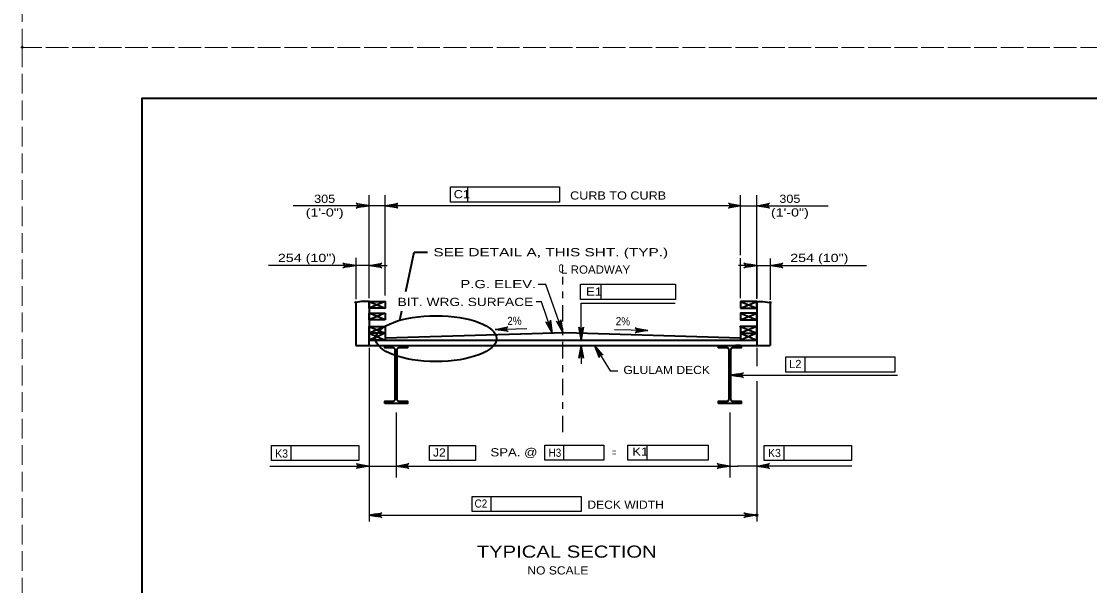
# Model space of a CAD drawing. Extents: x -11 to 79, y -154 to 0.
# Drawn here: x -0.01 to 15.61, y -73.87 to -65.62 of the extents above; entities that cross this region are included whole.
import ezdxf
from ezdxf.enums import TextEntityAlignment as Align

# ---------------------------------------------------------------- set-up
doc = ezdxf.new("R2010")
doc.units = 0
doc.header["$LTSCALE"] = 0.048
doc.header["$PDMODE"] = 32
doc.header["$PDSIZE"] = 0.024
doc.linetypes.add('DOT_DASHED', pattern=[7.7, 5, -1.2, 0.3, -1.2])
doc.linetypes.add('LONG_DASHED', pattern=[7.5, 6, -1.5])
for name, color, linetype, lineweight in [('1', 7, 'Continuous', 25), ('2', 7, 'Continuous', 35), ('3', 7, 'Continuous', 25), ('4', 7, 'Continuous', 25), ('6', 7, 'Continuous', 25), ('63', 7, 'LONG_DASHED', 13)]:
    doc.layers.add(name, color=color, linetype=linetype, lineweight=lineweight)
doc.layers.add('62', color=7, linetype='Continuous')

msp = doc.modelspace()

# ---------------------------------------------------------------- hatches: boundary and pattern name
at = {"layer": '2'}
for points in [[(4.96025, -68.29692), (4.96025, -68.33475), (5.07358, -68.31583)], [(10.39333, -68.29692), (10.39333, -68.33475), (10.50675, -68.31583)], [(10.85633, -68.29692), (10.85633, -68.33475), (10.74292, -68.31583)], [(4.76433, -69.173), (4.76433, -69.21083), (4.87767, -69.19192)], [(5.187, -69.173), (5.187, -69.21083), (5.07358, -69.19192)], [(10.62958, -69.173), (10.62958, -69.21083), (10.74292, -69.19192)], [(11.05225, -69.173), (11.05225, -69.21083), (10.93883, -69.19192)], [(7.05317, -70.14167), (7.05217, -70.10383), (6.93925, -70.12575)], [(8.98917, -70.12025), (8.98817, -70.158), (9.102, -70.14208)], [(8.19275, -70.16133), (8.155, -70.16133), (8.17392, -70.27475)], [(8.15583, -70.477), (8.19367, -70.477), (8.17475, -70.36358)], [(5.58075, -72.10567), (5.58075, -72.1435), (5.46733, -72.12458)], [(10.23583, -72.10567), (10.23583, -72.1435), (10.34925, -72.12458)], [(5.17875, -72.86108), (5.17875, -72.82608), (5.07358, -72.84358)], [(10.63775, -72.86108), (10.63775, -72.82608), (10.74292, -72.84358)]]:
    msp.add_hatch(color=256, dxfattribs=at).paths.add_polyline_path(points)
at = {"layer": '4'}
for points in [[(7.73375, -70.06542), (7.69808, -70.07792), (7.7535, -70.17867)], [(7.8885, -70.061), (7.85283, -70.0735), (7.90825, -70.17425)], [(8.41383, -70.46658), (8.44608, -70.44683), (8.37075, -70.36)], [(10.474, -70.81392), (10.474, -70.77617), (10.36067, -70.79508)]]:
    msp.add_hatch(color=256, dxfattribs=at).paths.add_polyline_path(points)
at = {"layer": '6'}
msp.add_hatch(color=256, dxfattribs=at).paths.add_polyline_path([(5.42325, -68.33475), (5.42325, -68.29692), (5.30983, -68.31583)])

# ---------------------------------------------------------------- linework, layer by layer
at = {"layer": '1', "lineweight": 35}
msp.add_lwpolyline([(1.75, -87.25), (33.25, -87.25), (33.25, -66.75), (1.75, -66.75)], close=True, dxfattribs=at)
at = {"layer": '2', "lineweight": 25}
for p, q in [((5.07358, -69.077), (5.07358, -68.16183)), ((5.30983, -69.62908), (5.30983, -68.16183)), ((10.50675, -69.038), (10.50675, -68.16183)), ((10.74292, -69.077), (10.74292, -68.16183)), ((5.30983, -68.31583), (3.96233, -68.31583)), ((10.39333, -68.31583), (5.30983, -68.31583)), ((10.50675, -68.31583), (11.78625, -68.31583)), ((5.07358, -69.19192), (3.60142, -69.19192)), ((4.87767, -69.07975), (4.87767, -69.68458)), ((5.07358, -69.67008), (5.07358, -69.08308)), ((5.187, -69.19192), (5.33975, -69.19192)), ((10.62958, -69.19192), (10.47683, -69.19192)), ((10.50675, -69.66767), (10.50675, -69.08308)), ((10.74292, -69.67675), (10.74292, -69.08308)), ((10.74292, -69.19192), (12.34925, -69.19192)), ((10.74292, -69.19508), (10.74292, -69.66633)), ((10.93883, -69.0905), (10.93883, -69.69183)), ((8.17392, -69.74075), (9.55233, -69.74075)), ((8.17392, -70.28133), (8.17392, -69.74075)), ((6.91817, -70.12625), (7.37992, -70.11425)), ((9.15258, -70.14375), (8.66308, -70.13008)), ((5.07358, -70.39292), (5.07358, -72.93825)), ((8.17475, -70.36), (8.17475, -70.62758)), ((10.74292, -70.39367), (10.74292, -70.66308)), ((10.74292, -70.88375), (10.74292, -72.93825)), ((5.46733, -71.33975), (5.46733, -72.23875)), ((10.34925, -71.33975), (10.34925, -72.23875)), ((5.46733, -71.88817), (5.46733, -72.29467)), ((10.34925, -71.88817), (10.34925, -72.29467)), ((3.62392, -72.12458), (5.07358, -72.12458)), ((5.07358, -72.12458), (10.472, -72.12458)), ((12.13342, -72.12458), (10.46258, -72.12458)), ((5.07358, -72.84358), (10.74292, -72.84358))]:
    msp.add_line(p, q, dxfattribs=at)
at = {"layer": '2', "linetype": 'DOT_DASHED', "lineweight": 25}
msp.add_line((7.90825, -71.62917), (7.90825, -69.35858), dxfattribs=at)
at = {"layer": '2', "lineweight": 25}
for points in [[(5.07008, -68.31525), (4.88367, -68.35017), (4.898, -68.34025), (4.90542, -68.32775), (4.90758, -68.31525), (4.90542, -68.30275), (4.898, -68.29025), (4.88367, -68.28033), (5.07008, -68.31525), (4.898, -68.29025), (4.90542, -68.30275), (5.07008, -68.31525), (4.90758, -68.31525), (4.90542, -68.32775), (5.07008, -68.31525), (4.898, -68.34025)], [(5.30983, -68.31583), (5.49625, -68.28092), (5.48192, -68.29083), (5.4745, -68.30333), (5.47233, -68.31583), (5.4745, -68.32833), (5.48192, -68.34083), (5.49625, -68.35075), (5.30983, -68.31583), (5.48192, -68.34083), (5.4745, -68.32833), (5.30983, -68.31583), (5.47233, -68.31583), (5.4745, -68.30333), (5.30983, -68.31583), (5.48192, -68.29083)], [(10.51717, -68.31583), (10.33075, -68.35075), (10.34508, -68.34083), (10.3525, -68.32833), (10.35467, -68.31583), (10.3525, -68.30333), (10.34508, -68.29083), (10.33075, -68.28092), (10.51717, -68.31583), (10.34508, -68.29083), (10.3525, -68.30333), (10.51717, -68.31583), (10.35467, -68.31583), (10.3525, -68.32833), (10.51717, -68.31583), (10.34508, -68.34083)], [(10.74292, -68.31583), (10.92933, -68.28092), (10.915, -68.29083), (10.90758, -68.30333), (10.90542, -68.31583), (10.90758, -68.32833), (10.915, -68.34083), (10.92933, -68.35075), (10.74292, -68.31583), (10.915, -68.34083), (10.90758, -68.32833), (10.74292, -68.31583), (10.90542, -68.31583), (10.90758, -68.30333), (10.74292, -68.31583), (10.915, -68.29083)], [(4.87767, -69.19192), (4.69125, -69.22683), (4.70558, -69.21692), (4.713, -69.20442), (4.71517, -69.19192), (4.713, -69.17942), (4.70558, -69.16692), (4.69125, -69.157), (4.87767, -69.19192), (4.70558, -69.16692), (4.713, -69.17942), (4.87767, -69.19192), (4.71517, -69.19192), (4.713, -69.20442), (4.87767, -69.19192), (4.70558, -69.21692)], [(5.07358, -69.19192), (5.26, -69.157), (5.24567, -69.16692), (5.23825, -69.17942), (5.23608, -69.19192), (5.23825, -69.20442), (5.24567, -69.21692), (5.26, -69.22683), (5.07358, -69.19192), (5.24567, -69.21692), (5.23825, -69.20442), (5.07358, -69.19192), (5.23608, -69.19192), (5.23825, -69.17942), (5.07358, -69.19192), (5.24567, -69.16692)], [(10.74292, -69.19192), (10.5565, -69.22683), (10.57083, -69.21692), (10.57825, -69.20442), (10.58042, -69.19192), (10.57825, -69.17942), (10.57083, -69.16692), (10.5565, -69.157), (10.74292, -69.19192), (10.57083, -69.16692), (10.57825, -69.17942), (10.74292, -69.19192), (10.58042, -69.19192), (10.57825, -69.20442), (10.74292, -69.19192), (10.57083, -69.21692)], [(10.93883, -69.19192), (11.12525, -69.157), (11.11092, -69.16692), (11.1035, -69.17942), (11.10133, -69.19192), (11.1035, -69.20442), (11.11092, -69.21692), (11.12525, -69.22683), (10.93883, -69.19192), (11.11092, -69.21692), (11.1035, -69.20442), (10.93883, -69.19192), (11.10133, -69.19192), (11.1035, -69.17942), (10.93883, -69.19192), (11.11092, -69.16692)], [(7.7535, -70.17867), (7.65875, -70.01433), (7.67292, -70.02458), (7.68717, -70.0275), (7.69967, -70.02533), (7.71075, -70.01917), (7.72008, -70.00808), (7.72475, -69.99117), (7.7535, -70.17867), (7.72008, -70.00808), (7.71075, -70.01917), (7.7535, -70.17867), (7.69967, -70.02533), (7.68717, -70.0275), (7.7535, -70.17867), (7.67292, -70.02458)], [(7.90742, -70.17192), (7.81267, -70.00758), (7.82683, -70.01783), (7.84108, -70.02075), (7.85358, -70.01858), (7.86467, -70.01242), (7.874, -70.00133), (7.87867, -69.98442), (7.90742, -70.17192), (7.874, -70.00133), (7.86467, -70.01242), (7.90742, -70.17192), (7.85358, -70.01858), (7.84108, -70.02075), (7.90742, -70.17192), (7.82683, -70.01783)], [(6.91817, -70.12625), (7.10358, -70.0865), (7.0895, -70.09675), (7.08242, -70.1095), (7.08058, -70.122), (7.08308, -70.1345), (7.09083, -70.14675), (7.10542, -70.15633), (6.91817, -70.12625), (7.09083, -70.14675), (7.08308, -70.1345), (6.91817, -70.12625), (7.08058, -70.122), (7.08242, -70.1095), (6.91817, -70.12625), (7.0895, -70.09675)], [(8.17392, -70.28133), (8.139, -70.09492), (8.14892, -70.10925), (8.16142, -70.11667), (8.17392, -70.11883), (8.18642, -70.11667), (8.19892, -70.10925), (8.20883, -70.09492), (8.17392, -70.28133), (8.19892, -70.10925), (8.18642, -70.11667), (8.17392, -70.28133), (8.17392, -70.11883), (8.16142, -70.11667), (8.17392, -70.28133), (8.14892, -70.10925)], [(9.15258, -70.14375), (8.96525, -70.1735), (8.97992, -70.16392), (8.98767, -70.15167), (8.99017, -70.13925), (8.98833, -70.12667), (8.98133, -70.11392), (8.96725, -70.10358), (9.15258, -70.14375), (8.98133, -70.11392), (8.98833, -70.12667), (9.15258, -70.14375), (8.99017, -70.13925), (8.98767, -70.15167), (9.15258, -70.14375), (8.97992, -70.16392)], [(8.17475, -70.36), (8.20967, -70.54642), (8.19975, -70.53208), (8.18725, -70.52467), (8.17475, -70.5225), (8.16225, -70.52467), (8.14975, -70.53208), (8.13983, -70.54642), (8.17475, -70.36), (8.14975, -70.53208), (8.16225, -70.52467), (8.17475, -70.36), (8.17475, -70.5225), (8.18725, -70.52467), (8.17475, -70.36), (8.19975, -70.53208)], [(8.37067, -70.36), (8.49783, -70.50075), (8.48183, -70.49367), (8.46733, -70.49392), (8.4555, -70.49858), (8.446, -70.50692), (8.43917, -70.51975), (8.43817, -70.53725), (8.37067, -70.36), (8.43917, -70.51975), (8.446, -70.50692), (8.37067, -70.36), (8.4555, -70.49858), (8.46733, -70.49392), (8.37067, -70.36), (8.48183, -70.49367)], [(10.36067, -70.79508), (10.54708, -70.76017), (10.53275, -70.77008), (10.52533, -70.78258), (10.52317, -70.79508), (10.52533, -70.80758), (10.53275, -70.82008), (10.54708, -70.83), (10.36067, -70.79508), (10.53275, -70.82008), (10.52533, -70.80758), (10.36067, -70.79508), (10.52317, -70.79508), (10.52533, -70.78258), (10.36067, -70.79508), (10.53275, -70.77008)], [(5.07358, -72.12458), (4.88717, -72.1595), (4.9015, -72.14958), (4.90892, -72.13708), (4.91108, -72.12458), (4.90892, -72.11208), (4.9015, -72.09958), (4.88717, -72.08967), (5.07358, -72.12458), (4.9015, -72.09958), (4.90892, -72.11208), (5.07358, -72.12458), (4.91108, -72.12458), (4.90892, -72.13708), (5.07358, -72.12458), (4.9015, -72.14958)], [(5.46733, -72.12458), (5.65375, -72.08967), (5.63942, -72.09958), (5.632, -72.11208), (5.62983, -72.12458), (5.632, -72.13708), (5.63942, -72.14958), (5.65375, -72.1595), (5.46733, -72.12458), (5.63942, -72.14958), (5.632, -72.13708), (5.46733, -72.12458), (5.62983, -72.12458), (5.632, -72.11208), (5.46733, -72.12458), (5.63942, -72.09958)], [(10.34925, -72.12458), (10.16283, -72.1595), (10.17717, -72.14958), (10.18458, -72.13708), (10.18675, -72.12458), (10.18458, -72.11208), (10.17717, -72.09958), (10.16283, -72.08967), (10.34925, -72.12458), (10.17717, -72.09958), (10.18458, -72.11208), (10.34925, -72.12458), (10.18675, -72.12458), (10.18458, -72.13708), (10.34925, -72.12458), (10.17717, -72.14958)], [(10.74292, -72.12458), (10.92933, -72.08967), (10.915, -72.09958), (10.90758, -72.11208), (10.90542, -72.12458), (10.90758, -72.13708), (10.915, -72.14958), (10.92933, -72.1595), (10.74292, -72.12458), (10.915, -72.14958), (10.90758, -72.13708), (10.74292, -72.12458), (10.90542, -72.12458), (10.90758, -72.11208), (10.74292, -72.12458), (10.915, -72.09958)], [(5.07358, -72.84358), (5.26, -72.80867), (5.24567, -72.81858), (5.23825, -72.83108), (5.23608, -72.84358), (5.23825, -72.85608), (5.24567, -72.86858), (5.26, -72.8785), (5.07358, -72.84358), (5.24567, -72.86858), (5.23825, -72.85608), (5.07358, -72.84358), (5.23608, -72.84358), (5.23825, -72.83108), (5.07358, -72.84358), (5.24567, -72.81858)], [(10.74292, -72.84358), (10.5565, -72.8785), (10.57083, -72.86858), (10.57825, -72.85608), (10.58042, -72.84358), (10.57825, -72.83108), (10.57083, -72.81858), (10.5565, -72.80867), (10.74292, -72.84358), (10.57083, -72.81858), (10.57825, -72.83108), (10.74292, -72.84358), (10.58042, -72.84358), (10.57825, -72.85608), (10.74292, -72.84358), (10.57083, -72.86858)]]:
    msp.add_lwpolyline(points, dxfattribs=at)
for points in [[(4.96025, -68.29692), (4.96025, -68.33475), (5.07358, -68.31583)], [(10.39333, -68.29692), (10.39333, -68.33475), (10.50675, -68.31583)], [(10.85633, -68.29692), (10.85633, -68.33475), (10.74292, -68.31583)], [(4.76433, -69.173), (4.76433, -69.21083), (4.87767, -69.19192)], [(5.187, -69.173), (5.187, -69.21083), (5.07358, -69.19192)], [(10.62958, -69.173), (10.62958, -69.21083), (10.74292, -69.19192)], [(11.05225, -69.173), (11.05225, -69.21083), (10.93883, -69.19192)], [(7.05317, -70.14167), (7.05217, -70.10383), (6.93925, -70.12575)], [(8.98917, -70.12025), (8.98817, -70.158), (9.102, -70.14208)], [(8.19275, -70.16133), (8.155, -70.16133), (8.17392, -70.27475)], [(8.15583, -70.477), (8.19367, -70.477), (8.17475, -70.36358)], [(5.58075, -72.10567), (5.58075, -72.1435), (5.46733, -72.12458)], [(10.23583, -72.10567), (10.23583, -72.1435), (10.34925, -72.12458)], [(5.17875, -72.86108), (5.17875, -72.82608), (5.07358, -72.84358)], [(10.63775, -72.86108), (10.63775, -72.82608), (10.74292, -72.84358)]]:
    msp.add_lwpolyline(points, close=True, dxfattribs=at)
at = {"layer": '2'}
msp.add_point((10.74292, -72.84358), dxfattribs=at)
at = {"layer": '3', "lineweight": 35}
for p, q in [((4.87767, -69.73183), (4.87767, -70.36)), ((5.07358, -69.71542), (5.07358, -70.28133)), ((5.30983, -69.71542), (5.07358, -69.81383)), ((5.07358, -69.71542), (5.30983, -69.81383)), ((10.50675, -69.71542), (10.50675, -69.81383)), ((10.74292, -69.71542), (10.50675, -69.71542)), ((10.50675, -69.81383), (10.74292, -69.71542)), ((10.50675, -69.71542), (10.74292, -69.81383)), ((10.50675, -69.81383), (10.74292, -69.81383)), ((10.74292, -69.71542), (10.74292, -70.36)), ((10.74292, -69.71542), (10.82492, -69.71542)), ((10.74292, -69.81383), (10.74292, -69.71542)), ((10.82492, -69.71542), (10.93883, -69.73183)), ((10.93883, -69.73183), (10.93883, -70.36)), ((5.07358, -69.98608), (5.07358, -69.88767)), ((5.07358, -69.88767), (5.30983, -69.88767)), ((5.30983, -69.88767), (5.07358, -69.98608)), ((5.30983, -69.98608), (5.07358, -69.88767)), ((5.30983, -69.98608), (5.07358, -69.98608)), ((5.30983, -69.88767), (5.30983, -69.98608)), ((10.50675, -69.88767), (10.74292, -69.98608)), ((10.50675, -69.98608), (10.74292, -69.88767)), ((5.07358, -70.18292), (5.07358, -70.0845)), ((5.07358, -70.0845), (5.30983, -70.0845)), ((5.30983, -70.0845), (5.07358, -70.18292)), ((5.30983, -70.0845), (5.30983, -70.18292)), ((10.50675, -70.0845), (10.50675, -70.18292)), ((10.74292, -70.0845), (10.50675, -70.0845)), ((10.50675, -70.0845), (10.74292, -70.18292)), ((10.74292, -70.18292), (10.74292, -70.0845)), ((5.07358, -70.36), (5.07358, -70.18292)), ((5.30983, -70.18292), (5.07358, -70.18292)), ((5.07358, -70.18292), (5.30983, -70.28133)), ((5.07358, -70.28133), (10.50675, -70.28133)), ((5.30983, -70.28133), (5.08892, -70.28133)), ((5.30983, -70.24858), (7.94767, -70.17308)), ((5.30983, -70.18292), (5.30983, -70.28133)), ((7.94767, -70.17308), (10.50675, -70.24858)), ((10.50675, -70.18292), (10.50675, -70.28133)), ((10.50675, -70.18292), (10.74292, -70.18292)), ((10.74292, -70.18292), (10.50675, -70.28133)), ((4.87767, -70.36), (10.93883, -70.36)), ((5.38533, -70.36), (5.54933, -70.36)), ((5.45592, -71.14508), (5.45592, -70.42617)), ((5.47875, -70.42617), (5.47875, -71.14508)), ((10.26725, -70.36), (10.43125, -70.36)), ((10.33783, -71.14508), (10.33783, -70.42617)), ((10.36067, -70.42617), (10.36067, -71.14508)), ((10.50342, -70.36), (10.43125, -70.36))]:
    msp.add_line(p, q, dxfattribs=at)
for points in [[(5.07358, -69.71542), (4.95975, -69.71542), (4.87767, -69.73183)], [(5.07358, -70.0845), (5.30983, -70.18292), (5.07358, -70.28133)], [(10.74292, -70.0845), (10.50675, -70.18292), (10.74292, -70.28133)], [(10.50675, -70.28133), (10.74292, -70.28133), (10.74292, -70.18292)], [(5.42642, -70.39667), (5.30158, -70.39667), (5.30158, -70.36), (5.63308, -70.36), (5.63308, -70.39667), (5.50825, -70.39667)], [(10.30825, -70.39667), (10.1835, -70.39667), (10.1835, -70.36), (10.515, -70.36), (10.515, -70.39667), (10.39017, -70.39667)], [(5.30158, -71.21125), (5.30158, -71.17458), (5.42642, -71.17458)], [(5.50825, -71.17458), (5.63308, -71.17458), (5.63308, -71.21125), (5.30158, -71.21125)], [(10.1835, -71.21125), (10.1835, -71.17458), (10.30825, -71.17458)], [(10.39017, -71.17458), (10.515, -71.17458), (10.515, -71.21125), (10.1835, -71.21125)]]:
    msp.add_lwpolyline(points, dxfattribs=at)
for points in [[(5.07358, -69.71542), (5.30983, -69.71542), (5.30983, -69.81383), (5.07358, -69.81383)], [(10.74292, -69.88767), (10.50675, -69.88767), (10.50675, -69.98608), (10.74292, -69.98608)]]:
    msp.add_lwpolyline(points, close=True, dxfattribs=at)
for centre, start, end in [((5.42635, -70.42618), 0, 90), ((5.50824, -70.42618), 90, 180), ((10.30826, -70.42618), 0, 90), ((10.39015, -70.42618), 90, 180), ((5.42635, -71.14507), 270, 0), ((5.50824, -71.14507), 180, 270), ((10.30826, -71.14507), 270, 0), ((10.39015, -71.14507), 180, 270)]:
    msp.add_arc(centre, 0.02953, start, end, dxfattribs=at)
at = {"layer": '3'}
for p in [(4.87767, -69.73183), (10.93883, -69.73183), (10.50675, -70.0845), (10.50675, -70.28133), (5.07358, -70.36)]:
    msp.add_point(p, dxfattribs=at)
at = {"layer": '4'}
for p, q in [((6.263, -68.04117), (7.8575, -68.04117)), ((6.263, -68.26267), (6.263, -68.04117)), ((6.51642, -68.26267), (6.51642, -68.04117)), ((7.8575, -68.04117), (7.8575, -68.26267)), ((7.8575, -68.26267), (6.263, -68.26267)), ((5.30983, -68.92817), (5.30983, -68.60967)), ((8.16542, -69.46433), (9.554, -69.46433)), ((8.16542, -69.68583), (8.16542, -69.46433)), ((8.46533, -69.68583), (8.46533, -69.46433)), ((9.554, -69.46433), (9.554, -69.68583)), ((7.59317, -69.72208), (7.51708, -69.72208)), ((7.7535, -70.17867), (7.59317, -69.72208)), ((9.554, -69.68583), (8.16542, -69.68583)), ((8.37067, -70.36), (8.59942, -70.73358)), ((11.17042, -70.52808), (12.76492, -70.52808)), ((11.17042, -70.7495), (11.17042, -70.52808)), ((11.4525, -70.7495), (11.4525, -70.52808)), ((12.76492, -70.52808), (12.76492, -70.7495)), ((8.59942, -70.73358), (8.71283, -70.73358)), ((12.76492, -70.7495), (11.17042, -70.7495)), ((10.36067, -70.79508), (12.80233, -70.79508)), ((3.64433, -71.82183), (4.92258, -71.82183)), ((3.64433, -72.04325), (3.64433, -71.82183)), ((3.93558, -72.04325), (3.93558, -71.82183)), ((4.92258, -71.82183), (4.92258, -72.04325)), ((5.95467, -71.82183), (6.62992, -71.82183)), ((5.95467, -72.04325), (5.95467, -71.82183)), ((6.23025, -72.04325), (6.23025, -71.82183)), ((6.62992, -71.82183), (6.62992, -72.04325)), ((7.64567, -71.81758), (8.505, -71.81758)), ((7.64567, -72.039), (7.64567, -71.81758)), ((7.92125, -72.039), (7.92125, -71.81758)), ((8.505, -71.81758), (8.505, -72.039)), ((8.85942, -71.81758), (10.0315, -71.81758)), ((8.85942, -72.039), (8.85942, -71.81758)), ((9.14142, -72.039), (9.14142, -71.81758)), ((10.0315, -71.81758), (10.0315, -72.039)), ((10.85267, -71.82183), (12.13092, -71.82183)), ((10.85267, -72.04325), (10.85267, -71.82183)), ((11.14383, -72.04325), (11.14383, -71.82183)), ((12.13092, -71.82183), (12.13092, -72.04325)), ((4.92258, -72.04325), (3.64433, -72.04325)), ((6.62992, -72.04325), (5.95467, -72.04325)), ((8.505, -72.039), (7.64567, -72.039)), ((10.0315, -72.039), (8.85942, -72.039)), ((12.13092, -72.04325), (10.85267, -72.04325)), ((6.58158, -72.56892), (8.17608, -72.56892)), ((6.58158, -72.79042), (6.58158, -72.56892)), ((6.85717, -72.79042), (6.85717, -72.56892)), ((8.17608, -72.56892), (8.17608, -72.79042)), ((8.17608, -72.79042), (6.58158, -72.79042))]:
    msp.add_line(p, q, dxfattribs=at)
at = {"layer": '4', "lineweight": 35}
for p, q in [((5.61275, -69.56967), (5.73175, -68.99733)), ((5.73175, -68.99733), (5.92842, -68.99733)), ((5.525, -69.99225), (5.5535, -69.85492))]:
    msp.add_line(p, q, dxfattribs=at)
at = {"layer": '4'}
msp.add_lwpolyline([(7.90742, -70.17192), (7.65992, -69.46717), (7.5465, -69.46717)], dxfattribs=at)
for points in [[(7.73375, -70.06542), (7.69808, -70.07792), (7.7535, -70.17867)], [(7.8885, -70.061), (7.85283, -70.0735), (7.90825, -70.17425)], [(8.41383, -70.46658), (8.44608, -70.44683), (8.37075, -70.36)], [(10.474, -70.81392), (10.474, -70.77617), (10.36067, -70.79508)]]:
    msp.add_lwpolyline(points, close=True, dxfattribs=at)
at = {"layer": '4', "lineweight": 35}
msp.add_ellipse((6.05415, -70.2607), major_axis=(-0.88457, 0), ratio=0.378749, dxfattribs=at)
at = {"layer": '6'}
msp.add_lwpolyline([(5.42325, -68.33475), (5.42325, -68.29692), (5.30983, -68.31583)], close=True, dxfattribs=at)
at = {"layer": '62'}
msp.add_point((0, -66), dxfattribs=at)
at = {"layer": '63'}
for points in [[(0, -66), (34, -66), (34, -44), (0, -44)], [(0, -88), (34, -88), (34, -66), (0, -66)]]:
    msp.add_lwpolyline(points, close=True, dxfattribs=at)

# ---------------------------------------------------------------- texts
at = {"layer": '4'}
for s, width, p in [('C1', 1.15, (6.31208, -68.20733)), ('SEE DETAIL A, THIS SHT. (TYP.)', 1.4, (6.01425, -69.05642)), ('C', 0.65, (7.84425, -69.2935)), ('L ROADWAY', 1.05, (7.88167, -69.3105)), ('P.G. ELEV.', 1.35, (6.40925, -69.52233)), ('E1', 1.2, (8.24583, -69.63225)), ('BIT. WRG. SURFACE', 1.25, (5.49058, -69.78375)), ('GLULAM DECK', 1.1, (8.79308, -70.77875)), ('J2', 1.1, (6.0085, -71.986)), ('K1', 1.2, (8.92242, -71.97375)), ('K3', 0.95, (3.70083, -72.00192)), ('K3', 0.95, (10.90917, -71.99392)), ('DECK WIDTH', 1.1, (8.26642, -72.75033)), ('NO SCALE', 1.1, (7.38825, -73.71133))]:
    msp.add_text(s, height=0.12, dxfattribs=dict(at, width=width)).set_placement(p)
for s, height, width, p in [('CURB TO CURB', 0.12, 1.15, (8.71588, -68.22667)), ('305', 0.12, 1.15, (4.42367, -68.27483)), ('305', 0.12, 1.15, (11.22758, -68.27483)), ('(1\'-0")', 0.12, 1.3, (4.42362, -68.47483)), ('(1\'-0")', 0.12, 1.3, (11.22754, -68.47483)), ('254 (10")', 0.12, 1.3, (4.165, -69.13958)), ('254 (10")', 0.12, 1.3, (11.65825, -69.13958)), ('SPA. @', 0.12, 1.2, (7.19217, -71.98358)), ('H3', 0.12, 0.9, (7.79154, -71.98967)), ('=', 0.12, 0.6, (8.65646, -71.98358)), ('C2', 0.12, 0.9, (6.70846, -72.73317)), ('TYPICAL SECTION', 0.1772, 1.25, (7.96437, -73.46533))]:
    msp.add_text(s, height=height, dxfattribs=dict(at, width=width)).set_placement(p, align=Align.CENTER)
at = {"layer": '4', "width": 0.9}
for rotation, p in [(1.504, (7.09633, -70.06292)), (358.496, (8.67958, -70.0635))]:
    msp.add_text('2%', height=0.12, rotation=rotation, dxfattribs=at).set_placement(p)
at = {"layer": '4'}
msp.add_text('L2', height=0.12, dxfattribs=at).set_placement((11.21758, -70.69225))

doc.saveas('drawing.dxf')
